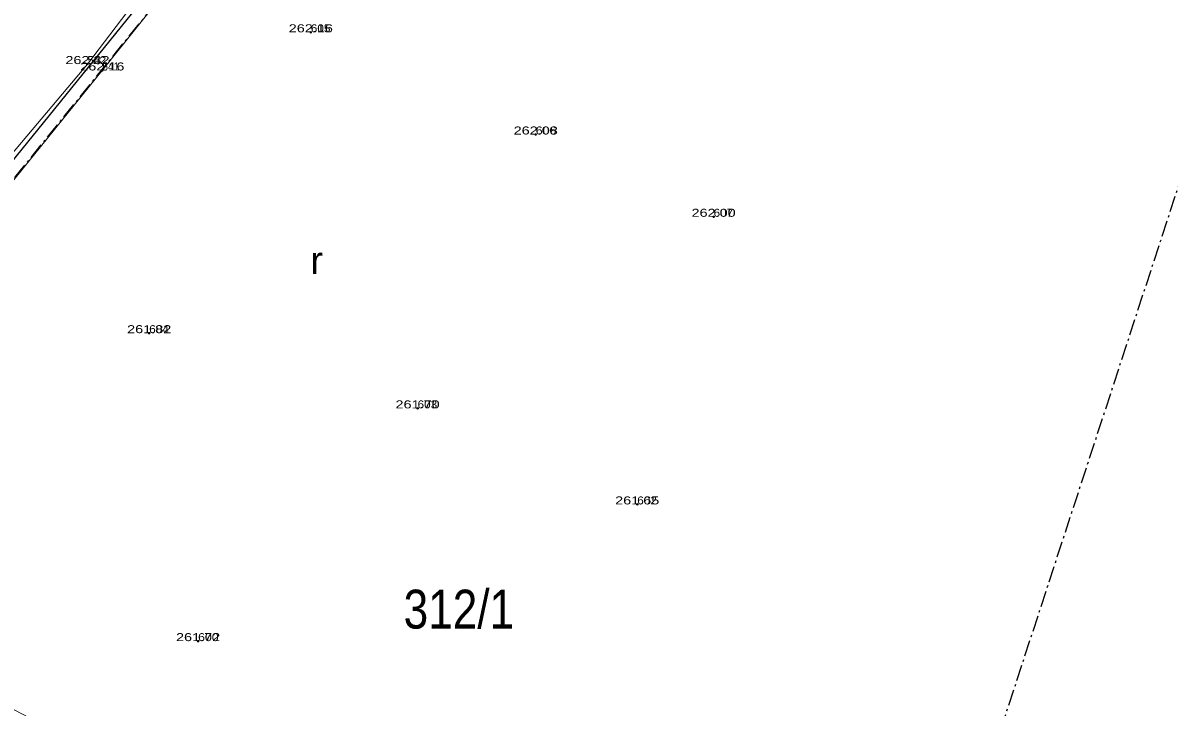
# Model space of a CAD drawing. Extents: x -568530 to -568223, y -1154101 to -1153740.
# Drawn here: x -568377.8 to -568327.6, y -1153916.3 to -1153886.3 of the extents above; entities that cross this region are included whole.
import ezdxf
from ezdxf.enums import TextEntityAlignment as Align

# ---------------------------------------------------------------- set-up
doc = ezdxf.new("R2010")
doc.units = 0
doc.header["$LTSCALE"] = 0.14
doc.header["$PDMODE"] = 32
doc.header["$PDSIZE"] = 0.07
doc.linetypes.add('DOT_DASHED', pattern=[7.7, 5, -1.2, 0.3, -1.2])
for name, color, linetype, lineweight in [('1', 7, 'Continuous', 25), ('11', 7, 'Continuous', 13), ('12', 7, 'Continuous', 13), ('14', 7, 'Continuous', 13), ('23', 7, 'Continuous', 13), ('36', 7, 'Continuous', 13), ('6', 7, 'DOT_DASHED', 25)]:
    doc.layers.add(name, color=color, linetype=linetype, lineweight=lineweight)
for name, color, linetype in [('13', 7, 'Continuous'), ('20', 7, 'Continuous'), ('49', 7, 'Continuous')]:
    doc.layers.add(name, color=color, linetype=linetype)

msp = doc.modelspace()

# ---------------------------------------------------------------- linework, layer by layer
at = {"layer": '1'}
msp.add_lwpolyline([(-568397.85, -1153916.62), (-568348.36, -1153855.52), (-568306.73, -1153803.52), (-568266.23, -1153754.08)], dxfattribs=at)
at = {"layer": '11'}
for p in [(-568365.16, -1153886.75), (-568374.93, -1153888.14), (-568374.28, -1153888.42), (-568355.32, -1153891.22), (-568347.54, -1153894.82), (-568372.23, -1153899.91), (-568360.49, -1153903.2), (-568350.88, -1153907.4), (-568370.09, -1153913.38)]:
    msp.add_point(p, dxfattribs=at)
at = {"layer": '14'}
msp.add_lwpolyline([(-568395.11, -1153912.31), (-568389.39, -1153905.01), (-568382.04, -1153896.57), (-568374.93, -1153888.14), (-568366.7, -1153877.32), (-568357.21, -1153865.06), (-568347.39, -1153851.22), (-568338.19, -1153841.21)], dxfattribs=at)
at = {"layer": '23'}
msp.add_lwpolyline([(-568354.04, -1153929.41), (-568364.61, -1153923.44), (-568379.16, -1153915.86), (-568390.37, -1153909.46), (-568387.81, -1153906.15), (-568381.36, -1153897.16), (-568374.28, -1153888.42), (-568365.82, -1153877.84), (-568356.68, -1153865.62), (-568346.38, -1153852.31), (-568338.19, -1153841.21)], dxfattribs=at)
at = {"layer": '6'}
msp.add_line((-568390.25, -1153908.12), (-568347.97, -1153855.84), dxfattribs=at)
msp.add_lwpolyline([(-568292.75, -1153788.12), (-568342.85, -1153941.3), (-568385.34, -1153912.52), (-568390.25, -1153908.12)], dxfattribs=at)

# ---------------------------------------------------------------- texts
at = {"layer": '12', "width": 1.35}
for s, p in [('262.16', (-568365.16, -1153886.75)), ('262.32', (-568374.93, -1153888.14)), ('262.16', (-568374.28, -1153888.42)), ('262.08', (-568355.32, -1153891.22)), ('262.00', (-568347.5395, -1153894.82)), ('261.82', (-568372.23, -1153899.91)), ('261.70', (-568360.4895, -1153903.2)), ('261.65', (-568350.8805, -1153907.4)), ('261.72', (-568370.09, -1153913.38))]:
    msp.add_text(s, height=0.35, dxfattribs=at).set_placement(p, align=Align.CENTER)
at = {"layer": '13'}
for s, width, p in [('605', 1.1, (-568365.16, -1153886.75)), ('542', 1.05, (-568374.93, -1153888.14)), ('541', 0.95, (-568374.28, -1153888.42)), ('606', 1.15, (-568355.32, -1153891.22)), ('607', 1.1, (-568347.54, -1153894.82)), ('604', 1.1, (-568372.23, -1153899.91)), ('603', 1.1, (-568360.49, -1153903.2)), ('602', 1.1, (-568350.88, -1153907.4)), ('600', 1.15, (-568370.09, -1153913.38))]:
    msp.add_text(s, height=0.35, dxfattribs=dict(at, width=width)).set_placement(p)
at = {"layer": '20', "width": 0.85}
msp.add_text('312/1', height=1.7, dxfattribs=at).set_placement((-568361.1, -1153912.83))
at = {"layer": '36'}
msp.add_text('r', height=1.2, dxfattribs=at).set_placement((-568364.9025, -1153897.319), align=Align.CENTER)
at = {"layer": '49', "width": 1.45}
msp.add_text('Sochorova', height=1.5, rotation=52.355, dxfattribs=at).set_placement((-568385.198, -1153888.782))

doc.saveas('drawing.dxf')
